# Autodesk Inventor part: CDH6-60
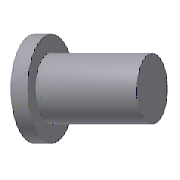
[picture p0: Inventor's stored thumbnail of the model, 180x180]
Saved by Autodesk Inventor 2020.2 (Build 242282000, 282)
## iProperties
Manager: www.cadconsulting.pl
Company: Fabian Stasiak CAD Consulting
IsCustomPart: 1
Created: 2014-02
Part Number: CDH6-60
Material: SKD61
Description: Straight Core Pin
Document SubType Name: Modeling
Designer: F.Stasiak
Standard Revision: 1
Manufacturer: PUNCH
Language: pl-PL
Size Designation: 6-60
Categories: <MemberInstance><Categories><Category DisplayName="Forma wtryskowa" InternalName="349578f2-f4d4-4954-8c09-8e99297a61c0" Mnemonic="MOLD"><Category DisplayName="W
Mass: 1.61494 g
Surface Area: 11.4822 cm^2
Volume: 1.61494 cm^3
Density: 7.8 g/cm^3
Appearance: Aluminium - ciemne
Catalog Web Link: www.expertbooks.pl
Author: F.Stasiak
Subject: Zbiór ćwiczeń. Autodesk Inventor 2020. Kurs Professional
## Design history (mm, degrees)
sketch "Sketch1"
  geometry: L1 (4.5, 0)-(4.5, 4); L2 (4.5, 4)-(3, 4); L3 (3, 4)-(3, 60); L4 (3, 60)-(0, 60); L5 (4.5, 0)-(0, 0); L6 (0, 0)-(0, 60); L7 (0, 60)-(0, -10) reference; 1 further point
  constraints: 14 end point, 2 horizontal, 1 coincident, 1 collinear, 1 parallel
  dimensions: "d2" = 4 distance of L1.start L1.end (= T_); "d19" = 60 distance between parallel lines of L4 L5 (= L); "d38" = 6 diameter of L3 L7 (= P); "d39" = 9 diameter of L1 L7 (= H_)
revolve "Revolution1" sketch "Sketch1" stored, may be unused: angle "d4" = 90 deg
fillet "Fillet1" dims "d36" = 0.3
workplane "Work Plane1"
sketch "Sketch2"
  geometry: 2 further points
  constraints: 1 vertical alignment
  dimensions: "d21" = 2 distance of point (0, -2) point (0, 0) (= 0.5 x T_)
hole "Anti_Rotary Hole" sketch "Sketch2" at (0, 0) diameter "d22" = 0.8 (= Anti_Rotary_D); stored, may be unused: countersink angle "d26" = 90 deg, drill point angle "d28" = 118 deg; dims "d23" = 6, "d24" = 4, "d25" = 2, "d27" = 1.2 (= 1.5 x Anti_Rotary_D)
sketch "Sketch3"
  geometry: L1 (-3.3, 3.059)-(-3.3, -3.059); A1 r 4.5 centre (0, 0) between (-3.3, 3.059) and (-3.3, -3.059) reference; 1 further point
  constraints: 2 end point, 2 point on circle, 1 vertical
  dimensions: "d29" = 3.3 distance from line of point (0, 0) L1 (= Anti_Rotary_P)
extrude "Anti_Rotary Plane" cut sketch "Sketch3" extent not by distance; stored distance "d30" = 10; taper "d31" = 0 deg
feature "Rzeźbienie3"
body "Solid1"
feature "Powierzchnia3"
body "Srf3"
other parameters: "H_" = 9 [user parameter; used in 1 equation term], "L" = 60 [user parameter; used in 1 equation term], "P" = 6 [user parameter; used in 1 equation term], "d7" = 0, "d8" = 0, "T_" = 4 [user parameter; used in 2 equation terms], "Anti_Rotary_P" = 3.3 [user parameter; used in 1 equation term], "Anti_Rotary_D" = 0.8 [user parameter; used in 2 equation terms], "d32" = 0, "d33" = 0, "d34" = 0, "d35" = 0, "IsARPlane" = 0 [user parameter], "IsARHole" = 0 [user parameter]
